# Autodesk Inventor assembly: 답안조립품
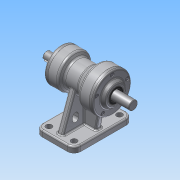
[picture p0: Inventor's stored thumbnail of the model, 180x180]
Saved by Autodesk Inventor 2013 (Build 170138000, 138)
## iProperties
Created: 2015-08
Part Number: 답안조립품
Document SubType Name: Assembly
Designer: Administrator
Author: Administrator
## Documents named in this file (10)
- C:\Users\Administrator\Desktop\450806V1028\답안조립품.iam
- C:\Users\Administrator\Desktop\450806V1028\M4x0.5.ipt
- C:\Users\Administrator\Desktop\450806V1028\뒤커버.ipt
- C:\Users\Administrator\Desktop\450806V1028\베어링 6203.ipt
- C:\Users\Administrator\Desktop\450806V1028\베어링 6205.ipt
- C:\Users\Administrator\Desktop\450806V1028\본체.ipt
- C:\Users\Administrator\Desktop\450806V1028\앞커버.ipt
- C:\Users\Administrator\Desktop\450806V1028\오일실 .ipt
- 오일실 .ipt
- C:\Users\Administrator\Desktop\450806V1028\축.ipt
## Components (10 placed, 1 different names)
1. M4x0.5:1
2. M4x0.5:3
3. M4x0.5:4
4. M4x0.5:5
5. M4x0.5:6
6. M4x0.5:2
7. M4x0.5:7
8. M4x0.5:8
9. M4x0.5:9
10. M4x0.5:10
